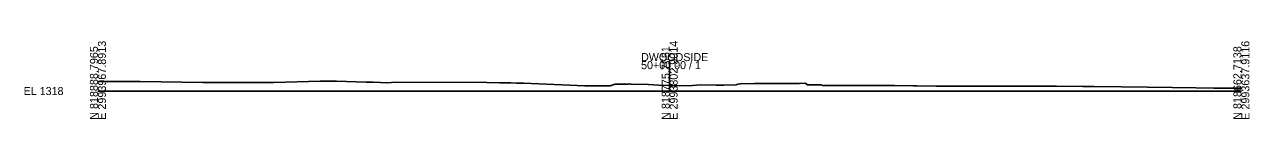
# Model space of a CAD drawing. Extents: x -26 to 2993816, y -55 to 819046.
# Drawn here: x -25.7 to 402.8, y 5990.3 to 6017.4 of the extents above; entities that cross this region are included whole.
import ezdxf

# ---------------------------------------------------------------- set-up
doc = ezdxf.new("R2010")
doc.units = 0
doc.layers.add('DESIGN - SHEET - Light Grid', color=7, linetype='Continuous')
doc.layers.add('SURVEY - GROUND - Top of Ground', color=7, linetype='Continuous')

msp = doc.modelspace()

# ---------------------------------------------------------------- linework, layer by layer
at = {"layer": 'DESIGN - SHEET - Light Grid'}
for p, q in [((200, 6000), (200, 6010.42)), ((0, 6000), (200, 6000)), ((200, 6000), (400, 6000))]:
    msp.add_line(p, q, dxfattribs=at)
at = {"layer": 'SURVEY - GROUND - Top of Ground'}
msp.add_lwpolyline([(0, 6003.32), (5.53, 6003.32), (12.66, 6003.31), (14.72, 6003.29), (36.67, 6003), (61.58, 6002.92), (77.74, 6003.47), (78.48, 6003.47), (83.5, 6003.41), (93.83, 6003.11), (96.24, 6003.14), (101.44, 6002.91), (103.93, 6003.09), (136.03, 6002.95), (140.44, 6002.83), (141.52, 6002.91), (144.43, 6002.8), (146.45, 6002.78), (148.85, 6002.72), (170.27, 6001.84), (173.45, 6001.83), (178.31, 6001.78), (179.19, 6001.85), (180.94, 6002.41), (185.64, 6002.42), (186.03, 6002.48), (186.39, 6002.35), (192.63, 6002.29), (196.04, 6002.02), (200, 6001.9), (202.22, 6001.82), (207.99, 6001.88), (210.77, 6002.1), (216.29, 6002.06), (218.91, 6002.04), (223.26, 6002.11), (223.85, 6002.4), (224.77, 6002.56), (229.71, 6002.59), (230.62, 6002.6), (234.74, 6002.67), (243.69, 6002.68), (244.37, 6002.63), (245.44, 6002.64), (247.4, 6002.79), (248.18, 6002.21), (252.06, 6002.18), (253.09, 6002.2), (253.33, 6001.97), (259.33, 6001.96), (271.56, 6001.97), (277.76, 6001.93), (278.66, 6001.88), (285.32, 6001.84), (286.51, 6001.77), (293.27, 6001.74), (301.68, 6001.71), (302.22, 6001.71), (308.32, 6001.71), (316.24, 6001.71), (324.44, 6001.71), (325.75, 6001.7), (335.37, 6001.64), (344.52, 6001.58), (347.05, 6001.55), (348.49, 6001.53), (358.09, 6001.41), (367.2, 6001.29), (375.86, 6001.18), (384.11, 6001.07), (390.41, 6001.02), (391.93, 6001.01), (400, 6000.96)], dxfattribs=at)

# ---------------------------------------------------------------- texts
at = {"layer": 'DESIGN - SHEET - Light Grid'}
for s, p in [('E 2993967.8913', (2.8, 5990)), ('E 2993802.9014', (202.8, 5990)), ('E 2993637.9116', (402.8, 5990)), ('N 818888.7965', (0, 5990)), ('N 818775.7551', (200, 5990)), ('N 818662.7138', (400, 5990))]:
    msp.add_text(s, height=2.8, rotation=90, dxfattribs=at).set_placement(p)
for s, p in [('DWOODSIDE', (190, 6010.42)), ('50+00.00 / 1', (190, 6007.62)), ('EL 1318', (-26, 5998.6))]:
    msp.add_text(s, height=2.8, dxfattribs=at).set_placement(p)

doc.saveas('drawing.dxf')
